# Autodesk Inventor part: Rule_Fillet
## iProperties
Created: 2008-12
Part Number: Rule_Fillet
Document SubType Name: Modeling
Designer: EAO
Density: 1 g/cm^3
Author: EAO
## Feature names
1. Extrusion1
2. Cup-Outer [Extrusion]
3. Cup-Inner [Extrusion]
4. Vent-Base [Extrusion]
5. FaceDraft1
6. Vent [Extrusion]
7. Vent-Meter [Hole]
8. Rectangular Pattern1
